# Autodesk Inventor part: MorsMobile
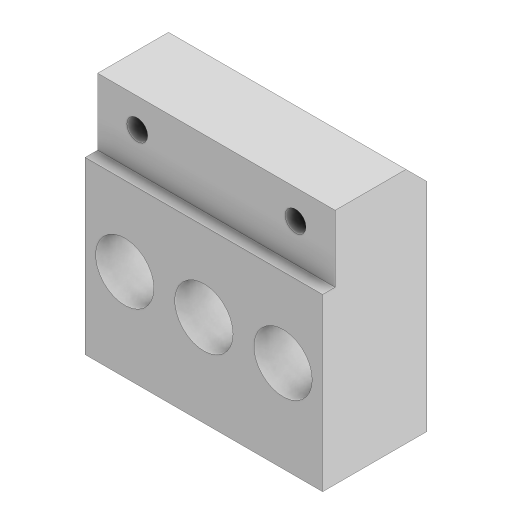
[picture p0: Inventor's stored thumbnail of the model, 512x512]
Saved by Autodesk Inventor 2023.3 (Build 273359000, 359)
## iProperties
Created: 2024-11
Part Number: MorsMobile
Material: Générique
Description: STEP AP203
Document SubType Name: Modeling
Designer: Thier
Density: 1 g/cm^3
Appearance: Par défaut
Title: MorsMobile.STEP
Revision Number: ANY
Sending System: SolidWorks 2017
Preprocessor: SwSTEP 2.0
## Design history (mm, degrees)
feature "Chanfrein1"
node "Solide1"
